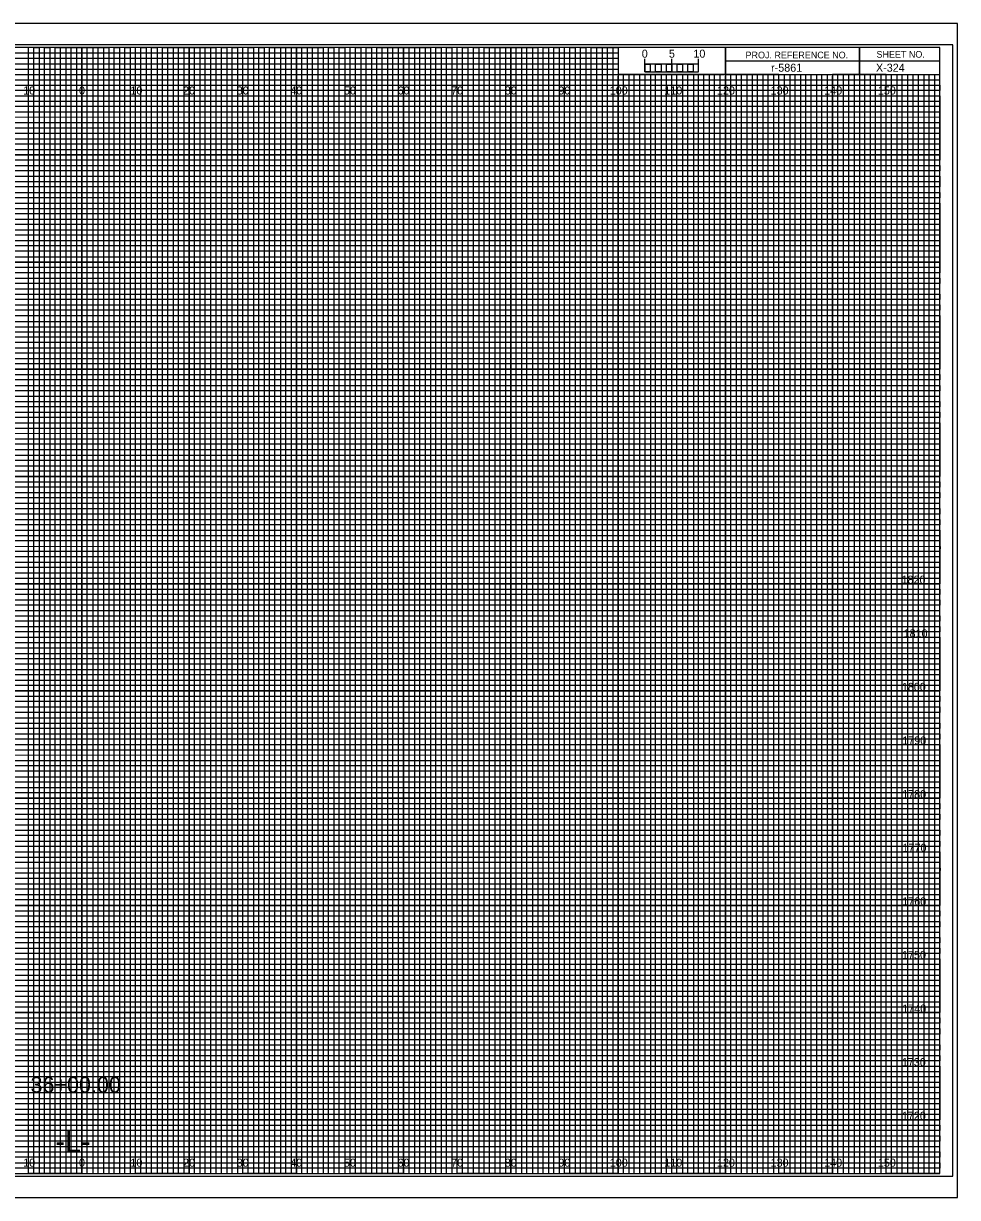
# Model space of a CAD drawing. Extents: x -15 to 323, y -5 to 6170.
# Drawn here: x 149.1 to 323.3, y 4395.5 to 4614.5 of the extents above; entities that cross this region are included whole.
import ezdxf

# ---------------------------------------------------------------- set-up
doc = ezdxf.new("R2010")
doc.units = 0
for name, color, linetype in [('Prop XS Alignment Label', 7, 'Continuous'), ('Prop XS Bar Scale Labels', 7, 'Continuous'), ('Prop XS DDE', 7, 'Continuous'), ('Prop XS DDE Earthwork Shape', 7, 'Continuous'), ('Prop XS DDE Slope Text', 7, 'Continuous'), ('Prop XS DDE Text', 7, 'Continuous'), ('Prop XS Earthwork Shape', 7, 'Continuous'), ('Prop XS Noise Wall', 7, 'Continuous'), ('Prop XS Project Number', 7, 'Continuous'), ('Prop XS Retaining Wall', 7, 'Continuous'), ('Prop XS Station Labels', 7, 'Continuous'), ('Prop XS Temporary Shoring', 7, 'Continuous'), ('Scratch_Level_3', 7, 'Continuous'), ('Scratch_Level_7', 7, 'Continuous'), ('Scratch_Level_8', 7, 'Continuous'), ('Sheet Cross Section Grid Minor 1 CELL', 7, 'Continuous')]:
    doc.layers.add(name, color=color, linetype=linetype)

msp = doc.modelspace()

# ---------------------------------------------------------------- linework, layer by layer
at = {"layer": 'Prop XS Alignment Label'}
for p, q in [((265, 4605.49), (265, 4607.9)), ((265, 4606.9), (265, 4607.9)), ((270, 4605.49), (270, 4607.9)), ((275, 4605.49), (275, 4607.9)), ((275, 4606.9), (275, 4607.9))]:
    msp.add_line(p, q, dxfattribs=at)
for points in [[(275, 4606.9), (265, 4606.9), (265, 4605.49), (275, 4605.49)], [(265, 4606.9), (266, 4606.9), (266, 4605.49), (265, 4605.49)], [(267, 4606.9), (268, 4606.9), (268, 4605.49), (267, 4605.49)], [(269, 4606.9), (270, 4606.9), (270, 4605.49), (269, 4605.49)], [(271, 4606.9), (272, 4606.9), (272, 4605.49), (271, 4605.49)], [(273, 4606.9), (274, 4606.9), (274, 4605.49), (273, 4605.49)]]:
    msp.add_lwpolyline(points, close=True, dxfattribs=at)
at = {"layer": 'Prop XS DDE'}
msp.add_lwpolyline([(-13.4, 4395.5), (323.3, 4395.5), (323.3, 4614.5), (-13.4, 4614.5)], close=True, dxfattribs=at)
at = {"layer": 'Prop XS DDE Slope Text'}
msp.add_lwpolyline([(-10.8, 4399.5), (322.4, 4399.5), (322.4, 4610.5), (-10.8, 4610.5)], close=True, dxfattribs=at)
at = {"layer": 'Prop XS DDE Text'}
for p, q in [((150, 4400), (150, 4610)), ((160, 4400), (160, 4610)), ((170, 4400), (170, 4610)), ((180, 4400), (180, 4610)), ((190, 4400), (190, 4610)), ((200, 4400), (200, 4610)), ((210, 4400), (210, 4610)), ((220, 4400), (220, 4610)), ((230, 4400), (230, 4610)), ((240, 4400), (240, 4610)), ((250, 4400), (250, 4610)), ((260, 4400), (260, 4604.69)), ((270, 4400), (270, 4604.69)), ((280, 4400), (280, 4604.69)), ((290, 4400), (290, 4604.69)), ((300, 4400), (300, 4604.69)), ((310, 4400), (310, 4604.69)), ((0, 4600), (320, 4600)), ((0, 4590), (320, 4590)), ((0, 4580), (320, 4580)), ((0, 4570), (320, 4570)), ((0, 4560), (320, 4560)), ((0, 4550), (320, 4550)), ((0, 4540), (320, 4540)), ((0, 4530), (320, 4530)), ((0, 4520), (320, 4520)), ((0, 4510), (320, 4510)), ((0, 4500), (320, 4500)), ((0, 4490), (320, 4490)), ((0, 4480), (320, 4480)), ((0, 4470), (320, 4470)), ((0, 4460), (320, 4460)), ((0, 4450), (320, 4450)), ((0, 4440), (320, 4440)), ((0, 4430), (320, 4430)), ((0, 4420), (320, 4420)), ((0, 4410), (320, 4410))]:
    msp.add_line(p, q, dxfattribs=at)
at = {"layer": 'Prop XS Earthwork Shape'}
for p, q in [((150, 4610), (140, 4610)), ((150, 4400), (150, 4610)), ((170, 4610), (160, 4610)), ((160, 4610), (160, 4400)), ((170, 4400), (170, 4610)), ((190, 4610), (180, 4610)), ((180, 4610), (180, 4400)), ((190, 4400), (190, 4610)), ((210, 4610), (200, 4610)), ((200, 4610), (200, 4400)), ((210, 4400), (210, 4610)), ((230, 4610), (220, 4610)), ((220, 4610), (220, 4400)), ((230, 4400), (230, 4610)), ((250, 4610), (240, 4610)), ((240, 4610), (240, 4400)), ((250, 4400), (250, 4610)), ((260, 4610), (260, 4400)), ((270, 4400), (270, 4605)), ((290, 4605), (280, 4605)), ((280, 4605), (280, 4400)), ((290, 4400), (290, 4605)), ((310, 4605), (300, 4605)), ((300, 4605), (300, 4400)), ((310, 4400), (310, 4605)), ((160, 4400), (150, 4400)), ((180, 4400), (170, 4400)), ((200, 4400), (190, 4400)), ((220, 4400), (210, 4400)), ((240, 4400), (230, 4400)), ((260, 4400), (250, 4400)), ((280, 4400), (270, 4400)), ((300, 4400), (290, 4400)), ((320, 4400), (310, 4400)), ((320, 4400), (320, 4400))]:
    msp.add_line(p, q, dxfattribs=at)
for points in [[(0, 4600), (320, 4600), (320, 4590), (0, 4590)], [(0, 4580), (320, 4580), (320, 4570), (0, 4570)], [(0, 4560), (320, 4560), (320, 4550), (0, 4550)], [(0, 4540), (320, 4540), (320, 4530), (0, 4530)], [(0, 4520), (320, 4520), (320, 4510), (0, 4510)], [(0, 4500), (320, 4500), (320, 4490), (0, 4490)], [(0, 4480), (320, 4480), (320, 4470), (0, 4470)], [(0, 4460), (320, 4460), (320, 4450), (0, 4450)], [(0, 4440), (320, 4440), (320, 4430), (0, 4430)], [(0, 4420), (320, 4420), (320, 4410), (0, 4410)]]:
    msp.add_lwpolyline(points, dxfattribs=at)
at = {"layer": 'Prop XS Noise Wall'}
for p, q in [((305, 4610), (305, 4605)), ((305, 4605), (305, 4610)), ((280, 4607.5), (280, 4605)), ((320, 4607.49), (280, 4607.49)), ((280, 4605), (320, 4605))]:
    msp.add_line(p, q, dxfattribs=at)
for points in [[(320, 4610), (0, 4610), (0, 4400), (320, 4400)], [(280, 4610), (260, 4610), (260, 4605.03), (280, 4605.03)], [(320, 4610), (280, 4610), (280, 4605), (320, 4605)]]:
    msp.add_lwpolyline(points, close=True, dxfattribs=at)
at = {"layer": 'Prop XS Retaining Wall'}
for p, q in [((267, 4605), (266.01, 4605)), ((266.01, 4605), (266.01, 4400)), ((267, 4400), (267, 4605)), ((269, 4605), (268, 4605)), ((268, 4605), (268, 4400)), ((269, 4400), (269, 4605)), ((266.01, 4400), (265, 4400)), ((268, 4400), (267, 4400))]:
    msp.add_line(p, q, dxfattribs=at)
for points in [[(150, 4400), (151, 4400), (151, 4610), (152, 4610), (152, 4400)], [(152, 4400), (153, 4400), (153, 4610), (154, 4610), (154, 4400)], [(155, 4400), (156, 4400), (156, 4610), (157, 4610), (157, 4400)], [(157, 4400), (158, 4400), (158, 4610), (159, 4610), (159, 4400)], [(160, 4400), (161, 4400), (161, 4610), (162, 4610), (162, 4400)], [(162, 4400), (163, 4400), (163, 4610), (164, 4610), (164, 4400)], [(165, 4400), (166, 4400), (166, 4610), (167, 4610), (167, 4400)], [(167, 4400), (168, 4400), (168, 4610), (169, 4610), (169, 4400)], [(170, 4400), (171, 4400), (171, 4610), (172, 4610), (172, 4400)], [(172, 4400), (173, 4400), (173, 4610), (174, 4610), (174, 4400)], [(175, 4400), (176, 4400), (176, 4610), (177, 4610), (177, 4400)], [(177, 4400), (178, 4400), (178, 4610), (179, 4610), (179, 4400)], [(180, 4400), (181, 4400), (181, 4610), (182, 4610), (182, 4400)], [(182, 4400), (183, 4400), (183, 4610), (184, 4610), (184, 4400)], [(185, 4400), (186, 4400), (186, 4610), (187, 4610), (187, 4400)], [(187, 4400), (188, 4400), (188, 4610), (189, 4610), (189, 4400)], [(190, 4400), (191, 4400), (191, 4610), (192, 4610), (192, 4400)], [(192, 4400), (193, 4400), (193, 4610), (194, 4610), (194, 4400)], [(195, 4400), (196, 4400), (196, 4610), (197, 4610), (197, 4400)], [(197, 4400), (198, 4400), (198, 4610), (199, 4610), (199, 4400)], [(200, 4400), (201, 4400), (201, 4610), (202, 4610), (202, 4400)], [(202, 4400), (203, 4400), (203, 4610), (204, 4610), (204, 4400)], [(205, 4400), (206, 4400), (206, 4610), (207, 4610), (207, 4400)], [(207, 4400), (208, 4400), (208, 4610), (209, 4610), (209, 4400)], [(210, 4400), (211, 4400), (211, 4610), (212, 4610), (212, 4400)], [(212, 4400), (213, 4400), (213, 4610), (214, 4610), (214, 4400)], [(215, 4400), (216, 4400), (216, 4610), (217, 4610), (217, 4400)], [(217, 4400), (218, 4400), (218, 4610), (219, 4610), (219, 4400)], [(220, 4400), (221, 4400), (221, 4610), (222, 4610), (222, 4400)], [(222, 4400), (223, 4400), (223, 4610), (224, 4610), (224, 4400)], [(225, 4400), (226, 4400), (226, 4610), (227, 4610), (227, 4400)], [(227, 4400), (228, 4400), (228, 4610), (229, 4610), (229, 4400)], [(230, 4400), (231, 4400), (231, 4610), (232, 4610), (232, 4400)], [(232, 4400), (233, 4400), (233, 4610), (234, 4610), (234, 4400)], [(235, 4400), (236, 4400), (236, 4610), (237, 4610), (237, 4400)], [(237, 4400), (238, 4400), (238, 4610), (239, 4610), (239, 4400)], [(240, 4400), (241, 4400), (241, 4610), (242, 4610), (242, 4400)], [(242, 4400), (243, 4400), (243, 4610), (244, 4610), (244, 4400)], [(245, 4400), (246, 4400), (246, 4610), (247, 4610), (247, 4400)], [(247, 4400), (248, 4400), (248, 4610), (249, 4610), (249, 4400)], [(250, 4400), (251, 4400), (251, 4610), (252, 4610), (252, 4400)], [(252, 4400), (253, 4400), (253, 4610), (254, 4610), (254, 4400)], [(255, 4400), (256, 4400), (256, 4610), (257, 4610), (257, 4400)], [(257, 4400), (258, 4400), (258, 4610), (259, 4610), (259, 4400)], [(260, 4400), (261, 4400), (261, 4605), (262.02, 4605), (262.02, 4400)], [(262, 4400), (263, 4400), (263, 4605), (263.99, 4605), (263.99, 4400)], [(270, 4400), (270.98, 4400), (270.98, 4605), (272, 4605), (272, 4400)], [(272, 4400), (273, 4400), (273, 4605), (274.05, 4605), (274.05, 4400)], [(275, 4400), (276, 4400), (276, 4605), (277, 4605), (277, 4400)], [(277, 4400), (278, 4400), (278, 4605), (279, 4605), (279, 4400)], [(280, 4400), (281, 4400), (281, 4605), (282, 4605), (282, 4400)], [(282, 4400), (283, 4400), (283, 4605), (284, 4605), (284, 4400)], [(285, 4400), (286, 4400), (286, 4605), (287, 4605), (287, 4400)], [(287, 4400), (288, 4400), (288, 4605), (289, 4605), (289, 4400)], [(290, 4400), (291, 4400), (291, 4605), (292, 4605), (292, 4400)], [(292, 4400), (293, 4400), (293, 4605), (294, 4605), (294, 4400)], [(295, 4400), (296, 4400), (296, 4605), (297, 4605), (297, 4400)], [(297, 4400), (298, 4400), (298, 4605), (299, 4605), (299, 4400)], [(300, 4400), (301, 4400), (301, 4605), (302, 4605), (302, 4400)], [(302, 4400), (303, 4400), (303, 4605), (304, 4605), (304, 4400)], [(305, 4400), (306, 4400), (306, 4605), (307, 4605), (307, 4400)], [(307, 4400), (308, 4400), (308, 4605), (309, 4605), (309, 4400)], [(310, 4400), (311, 4400), (311, 4605), (312, 4605), (312, 4400)], [(312, 4400), (313, 4400), (313, 4605), (314, 4605), (314, 4400)], [(315, 4400), (316, 4400), (316, 4605), (317, 4605), (317, 4400)], [(317, 4400), (318, 4400), (318, 4605), (319, 4605), (319, 4400)]]:
    msp.add_lwpolyline(points, dxfattribs=at)
at = {"layer": 'Prop XS Station Labels'}
for points in [[(145, 4400), (155, 4400), (155, 4610), (165, 4610), (165, 4400), (175, 4400), (175, 4610), (185, 4610), (185, 4400), (195, 4400), (195, 4610), (205, 4610), (205, 4400), (215, 4400), (215, 4610), (225, 4610), (225, 4400), (235, 4400), (235, 4610), (245, 4610), (245, 4400), (255, 4400), (255, 4610), (259.93, 4610), (260, 4610), (260, 4605), (264.99, 4605), (264.99, 4400), (275, 4400), (275, 4605), (285, 4605), (285, 4400), (295, 4400), (295, 4605), (305, 4605), (305, 4400), (315, 4400), (315, 4605)], [(0, 4605), (275, 4605)], [(0, 4585), (320, 4585), (320, 4595), (0, 4595)], [(0, 4565), (320, 4565), (320, 4575), (0, 4575)], [(0, 4545), (320, 4545), (320, 4555), (0, 4555)], [(0, 4525), (320, 4525), (320, 4535), (0, 4535)], [(0, 4505), (320, 4505), (320, 4515), (0, 4515)], [(0, 4485), (320, 4485), (320, 4495), (0, 4495)], [(0, 4465), (320, 4465), (320, 4475), (0, 4475)], [(0, 4445), (320, 4445), (320, 4455), (0, 4455)], [(0, 4425), (320, 4425), (320, 4435), (0, 4435)], [(0, 4405), (320, 4405), (320, 4415), (0, 4415)]]:
    msp.add_lwpolyline(points, dxfattribs=at)
at = {"layer": 'Scratch_Level_7'}
for p, q in [((323.3, 4614.5), (-13.4, 4614.5)), ((-13.4, 4395.5), (323.3, 4395.5))]:
    msp.add_line(p, q, dxfattribs=at)
at = {"layer": 'Sheet Cross Section Grid Minor 1 CELL'}
for p, q in [((0, 4609), (260, 4609)), ((260, 4607.98), (0, 4607.98)), ((260, 4609), (260, 4607.98)), ((0, 4607), (260, 4607)), ((260, 4605.89), (0, 4605.89)), ((260, 4607), (260, 4605.89)), ((0, 4604), (320, 4604))]:
    msp.add_line(p, q, dxfattribs=at)
for points in [[(0, 4603), (270, 4603), (320, 4603), (320, 4602), (0, 4602)], [(0, 4601), (320, 4601), (320, 4599), (0, 4599)], [(0, 4598), (320, 4598), (320, 4597), (0, 4596.98)], [(0, 4596), (320, 4596), (320, 4594), (0, 4594)], [(0, 4593), (320, 4593), (320, 4592), (0, 4592)], [(0, 4591), (320, 4591), (320, 4589), (0, 4589)], [(0, 4588), (320, 4588), (320, 4587), (0, 4587)], [(0, 4586), (320, 4586), (320, 4584), (0, 4584)], [(0, 4583), (320, 4583), (320, 4582), (0, 4582)], [(0, 4581), (320, 4581), (320, 4579), (0, 4579)], [(0, 4578), (320, 4578), (320, 4577), (0, 4577)], [(0, 4576), (320, 4576), (320, 4573.95), (320, 4573), (320, 4572), (0, 4572)], [(0, 4574), (320, 4574), (320, 4573), (0, 4573)], [(0, 4571), (320, 4571), (320, 4569), (0, 4569.03)], [(0, 4569.03), (320, 4569), (320, 4568), (0, 4568)], [(0, 4567), (320, 4567), (320, 4566), (0, 4566)], [(0, 4564), (320, 4564), (320, 4563), (0, 4563)], [(0, 4562), (320, 4562), (320, 4561), (0, 4561)], [(-0.07, 4558.89), (320, 4558.89), (320, 4557.88), (-0.07, 4557.88)], [(0, 4557), (320, 4557), (320, 4556), (0, 4556)], [(0, 4554), (320, 4554), (320, 4553), (0, 4553)], [(0, 4552), (320, 4552), (320, 4551), (0, 4551)], [(0, 4549), (320, 4549), (320, 4548), (0, 4548)], [(0, 4547), (320, 4547), (320, 4546), (0, 4546)], [(0, 4544), (320, 4544), (320, 4543), (0, 4543)], [(0, 4542), (320, 4542), (320, 4541), (0, 4541)], [(0, 4539), (320, 4539), (319.99, 4537.98), (0, 4538)], [(0, 4537), (320, 4537), (320, 4536), (0, 4536)], [(0, 4534), (320, 4534), (320, 4533), (0, 4533)], [(0, 4532), (320, 4532), (320, 4531), (0, 4531)], [(0, 4529), (320, 4529), (320, 4528), (0, 4528)], [(0, 4527), (320, 4527), (320, 4526), (0, 4526)], [(0, 4524), (320, 4524), (320, 4523), (0, 4523)], [(0, 4522), (320, 4522), (320, 4521), (0, 4521)], [(0, 4519), (320, 4519), (320, 4518), (0, 4518)], [(0, 4516.99), (320.07, 4516.91), (320, 4516), (0, 4516)], [(0, 4514), (320, 4514), (320, 4513), (0, 4513)], [(0, 4512), (320, 4512), (320, 4511), (0, 4511)], [(0, 4509), (320, 4509), (320, 4508), (0, 4508)], [(0, 4507), (320, 4507), (320, 4506), (0, 4506)], [(0, 4504), (320, 4504), (320, 4503), (0, 4503)], [(0, 4502), (320, 4502), (320, 4501), (0, 4501)], [(0, 4499), (320, 4499), (320, 4498), (0, 4498)], [(0, 4497), (320, 4497), (320, 4496), (0, 4496)], [(0, 4494), (320, 4494), (320, 4493), (0, 4493)], [(0, 4492), (320, 4492), (320, 4491), (0, 4491)], [(0, 4489), (320, 4489), (320, 4488), (0, 4488)], [(0, 4487), (320, 4487), (320, 4486), (0, 4486)], [(0, 4484), (320, 4484), (320, 4483), (0, 4483)], [(0, 4482), (320, 4482), (320, 4481), (0, 4481)], [(0, 4479), (320, 4479), (319.99, 4477.98), (0, 4478)], [(0, 4477), (320, 4477), (320, 4476), (0, 4476)], [(0, 4474), (320, 4474), (320, 4473), (0, 4473)], [(0, 4472), (320, 4472), (320, 4471), (0, 4471)], [(0, 4469), (320, 4469), (320, 4468), (0, 4468)], [(0, 4467), (320, 4467), (320, 4466), (0, 4466)], [(0, 4464), (320, 4464), (320, 4463), (0, 4463)], [(0, 4462), (320, 4462), (320, 4461), (0, 4461)], [(0, 4459), (320, 4459), (320, 4458), (0, 4458)], [(0, 4456.99), (320.07, 4456.91), (320, 4456), (0, 4456)], [(0, 4454), (320, 4454), (320, 4453), (0, 4453)], [(0, 4452), (320, 4452), (320, 4451), (0, 4451)], [(0, 4449), (320, 4449), (320, 4448), (0, 4448)], [(0, 4447), (320, 4447), (320, 4446), (0, 4446)], [(0, 4444), (320, 4444), (320, 4443), (0, 4443)], [(0, 4442), (320, 4442), (320, 4441), (0, 4441)], [(0, 4439), (320, 4439), (320, 4438), (0, 4438)], [(0, 4437), (320, 4437), (320, 4436), (0, 4436)], [(0, 4434), (320, 4434), (320, 4433), (0, 4433)], [(0, 4432), (320, 4432), (320, 4431), (0, 4431)], [(0, 4429), (320, 4429), (320, 4428), (0, 4428)], [(0, 4427), (320, 4427), (320, 4426), (0, 4426)], [(0, 4424), (320, 4424), (320, 4423), (0, 4423)], [(0, 4422), (320, 4422), (320, 4421), (0, 4421)], [(0, 4419), (320, 4419), (320, 4418), (0, 4418)], [(0, 4417), (320, 4417), (320, 4416), (0, 4416)], [(0, 4414), (320, 4414), (320, 4413), (0, 4413)], [(0, 4412), (320, 4412), (320, 4411), (0, 4411)], [(0, 4409), (320, 4409), (320, 4408), (0, 4408)], [(0, 4407), (320, 4407), (320, 4406), (0, 4406)], [(0, 4404), (320, 4404), (320, 4403), (0, 4403)], [(0, 4402), (320, 4402), (320, 4401), (0, 4401)]]:
    msp.add_lwpolyline(points, dxfattribs=at)

# ---------------------------------------------------------------- texts
at = {"layer": 'Prop XS Alignment Label'}
for s, height, p in [('0', 1.5, (264.41, 4608.12)), ('-L-', 4, (155.06, 4404))]:
    msp.add_text(s, height=height, dxfattribs=at).set_placement(p)
at = {"layer": 'Prop XS Bar Scale Labels'}
for s, p in [('5', (269.47, 4608.12)), ('10', (274.04, 4608.12))]:
    msp.add_text(s, height=1.5, dxfattribs=at).set_placement(p)
at = {"layer": 'Prop XS DDE Earthwork Shape'}
msp.add_text('X-324', height=1.5, dxfattribs=at).set_placement((308.09, 4605.5))
at = {"layer": 'Prop XS Noise Wall'}
for s, p in [('PROJ. REFERENCE NO.', (283.77, 4607.99)), ('SHEET NO.', (308.19, 4608.12))]:
    msp.add_text(s, height=1.25, dxfattribs=at).set_placement(p)
at = {"layer": 'Prop XS Project Number'}
msp.add_text('r-5861', height=1.5, dxfattribs=at).set_placement((288.53, 4605.5))
at = {"layer": 'Prop XS Temporary Shoring'}
msp.add_text('36+00.00', height=3, dxfattribs=at).set_placement((150.41, 4415.04))
at = {"layer": 'Scratch_Level_3'}
for s, p in [('1820', (312.87, 4510)), ('1810', (313.25, 4500)), ('1800', (312.92, 4490)), ('1790', (313, 4480)), ('1780', (312.98, 4470)), ('1770', (313.04, 4460)), ('1760', (313, 4450)), ('1750', (312.96, 4440)), ('1740', (313, 4430)), ('1730', (312.92, 4420)), ('1720', (312.93, 4410))]:
    msp.add_text(s, height=1.5, dxfattribs=at).set_placement(p)
at = {"layer": 'Scratch_Level_8'}
for s, p in [('10', (149.04, 4601.25)), ('0', (159.45, 4601.25)), ('0', (159.45, 4601.25)), ('10', (169.04, 4601.25)), ('20', (178.86, 4601.25)), ('30', (188.86, 4601.25)), ('40', (198.86, 4601.25)), ('50', (208.86, 4601.25)), ('60', (218.86, 4601.25)), ('70', (228.86, 4601.25)), ('80', (238.86, 4601.25)), ('90', (248.86, 4601.25)), ('100', (258.44, 4601.25)), ('110', (268.62, 4601.25)), ('120', (278.44, 4601.25)), ('130', (288.44, 4601.25)), ('140', (298.44, 4601.25)), ('150', (308.44, 4601.25)), ('10', (149.04, 4401.25)), ('0', (159.45, 4401.25)), ('0', (159.45, 4401.25)), ('10', (169.04, 4401.25)), ('20', (178.86, 4401.25)), ('30', (188.86, 4401.25)), ('40', (198.86, 4401.25)), ('50', (208.86, 4401.25)), ('60', (218.86, 4401.25)), ('70', (228.86, 4401.25)), ('80', (238.86, 4401.25)), ('90', (248.86, 4401.25)), ('100', (258.44, 4401.25)), ('110', (268.62, 4401.25)), ('120', (278.44, 4401.25)), ('130', (288.44, 4401.25)), ('140', (298.44, 4401.25)), ('150', (308.44, 4401.25))]:
    msp.add_text(s, height=1.5, dxfattribs=at).set_placement(p)

doc.saveas('drawing.dxf')
